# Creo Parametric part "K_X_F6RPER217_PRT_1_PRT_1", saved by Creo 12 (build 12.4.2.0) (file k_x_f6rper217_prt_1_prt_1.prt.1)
Units: Custom; MM, KILOGRAM, SECS

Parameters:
  PTC_WM_ITERATION = "0"
  PTC_WM_VERSION = "-.0"
  PTC_WM_LIFECYCLE_STATE = "In Work"
  PTC_WM_LIFECYCLE = "MO_CADDocument"
  PTC_WM_CREATED_BY = "Maximilian Roepper (Z0017RMS: MO)"
  PTC_WM_CREATED_ON = "18-Sep-26 11:36:42 AM"
  PTC_WM_MODIFIED_BY = "Maximilian Roepper (Z0017RMS: MO)"
  PTC_WM_MODIFIED_ON = "18-Sep-26 11:36:46 AM"
  PDMLINKNUMBER = "PDM000071455145"
  PTC_WM_NAME = "k_x_f6rper217_prt_1_prt_1.prt"
  PTC_WM_NUMBER = "PDM000071455145"

Other parameters: WEIGHT, WEIGHT_FACTOR, WEIGHT_ADD, _MASS_TEMP, _DIFF_TEMP, MC_ERRORS, SUPPLIER

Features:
  1. coordinate system
  2. datum plane "PRT_YZ"
  3. datum plane "PRT_XY"
  4. datum plane "PRT_XZ"
  5. coordinate system
  6. datum axis
  7. datum axis
  8. datum axis
  9. coordinate system
  10. imported feature
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
Other named items: PRT, SIEMENS_MO, DRW_VIEW_ORG, PRT_X, PRT_Y, PRT_Z, CS0, ROUGH_GROB

Layers: 00_STD_CSYS-KSYS, 01_STD_PLANES-EBENEN, 02_STD_AXES-ACHSEN, 03_STD_CSYS-KSYS, 24_IMPORT_FEAT-IMPORT_KE

Surfaces: 16 tabulated cylinder, 4 plane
